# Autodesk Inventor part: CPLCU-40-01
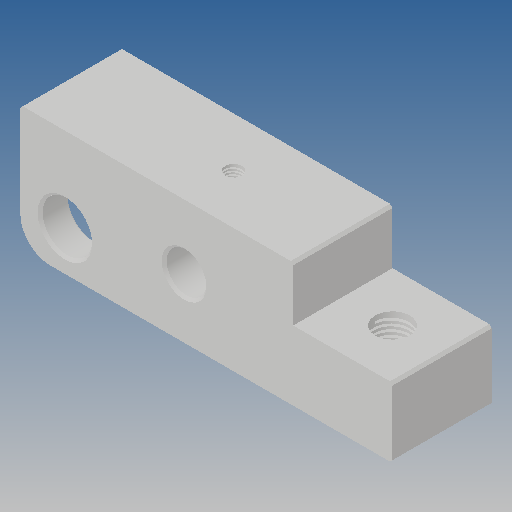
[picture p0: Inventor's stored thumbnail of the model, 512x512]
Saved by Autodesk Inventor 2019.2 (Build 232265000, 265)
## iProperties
Created: 2010-03
Part Number: CPLCU-40-01
Material: Ogólny
Document SubType Name: Modeling
Designer: CADENGINEERING4
Density: 1 g/cm^3
Appearance: Domyślna
Author: CADENGINEERING4
Revision Number: 1LAST_VERSION
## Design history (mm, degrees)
feature "Baza1"
node "Bryła1"
